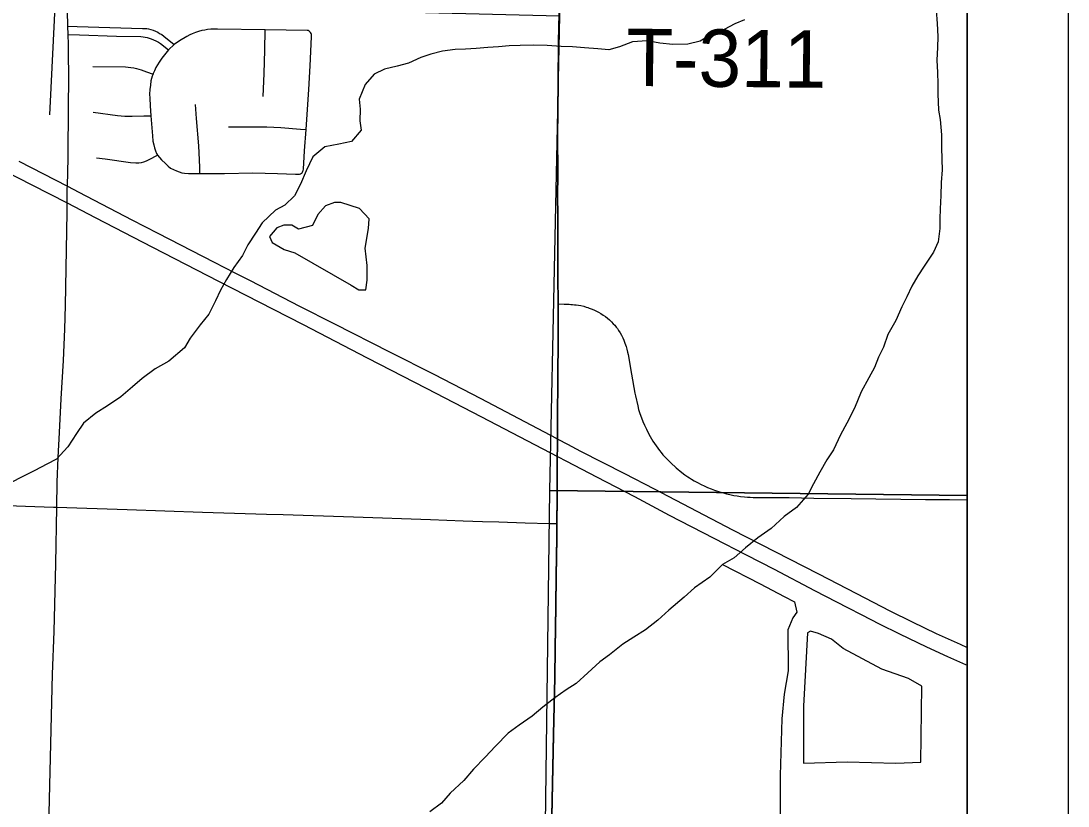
# Model space of a CAD drawing. Extents: x 0 to 34, y 0 to 22.
# Drawn here: x 7.962 to 9, y 16.1 to 16.878 of the extents above; entities that cross this region are included whole.
import ezdxf

# ---------------------------------------------------------------- set-up
doc = ezdxf.new("R2010")
doc.units = 0
for name, color, linetype in [('GM_X_Corporation', 7, 'Continuous'), ('GM_X_County_Road', 7, 'Continuous'), ('GM_X_Interstate_Route', 7, 'Continuous'), ('GM_X_Minor_Lake', 7, 'Continuous'), ('GM_X_Minor_River', 7, 'Continuous'), ('GM_X_Township_Road', 7, 'Continuous'), ('GM_X_Township_Road_Text', 7, 'Continuous'), ('SH_Data', 7, 'Continuous')]:
    doc.layers.add(name, color=color, linetype=linetype)

msp = doc.modelspace()

# ---------------------------------------------------------------- linework, layer by layer
at = {"layer": 'GM_X_Corporation'}
for points in [[(2.1, 14.1), (8.9, 14.1), (8.9, 20.9), (5.8906, 20.9)], [(8.9, 14.3789), (8.9, 20.9)], [(8.496, 16.9136), (8.4946, 16.8569), (8.4944, 16.8165), (8.4939, 16.763), (8.494, 16.7276), (8.4939, 16.7021), (8.494, 16.6872), (8.4942, 16.6244), (8.4943, 16.5979), (8.4943, 16.5579), (8.494, 16.5287), (8.4938, 16.4783), (8.4937, 16.4639), (8.4937, 16.4541), (8.4936, 16.4468), (8.4936, 16.4298), (8.4936, 16.405), (8.4932, 16.3802), (8.493, 16.3658), (8.4926, 16.3279), (8.4922, 16.2981), (8.4916, 16.2558), (8.491, 16.2272), (8.4897, 16.1707), (8.4889, 16.1222), (8.4875, 16.0575)], [(8.4875, 16.0575), (8.4889, 16.1222), (8.4897, 16.1707), (8.491, 16.2272), (8.4916, 16.2558), (8.4922, 16.2981), (8.4926, 16.3279), (8.493, 16.3658), (8.4932, 16.3802), (8.4936, 16.405), (8.4936, 16.4298), (8.4936, 16.4468), (8.4937, 16.4541), (8.4937, 16.4639), (8.4938, 16.4783), (8.494, 16.5287), (8.4943, 16.5579), (8.4943, 16.5979), (8.4942, 16.6244), (8.494, 16.6872), (8.4939, 16.7021), (8.494, 16.7276), (8.4939, 16.763), (8.4944, 16.8165), (8.4946, 16.8569), (8.496, 16.9136)]]:
    msp.add_lwpolyline(points, dxfattribs=at)
for points in [[(8.9, 16.4075), (8.9, 17.4164), (8.5049, 17.4227), (8.4956, 16.8828), (8.4859, 16.4125)], [(7.4991, 16.9078), (8.4956, 16.8828), (8.4859, 16.4125), (8.4788, 15.8782), (7.4758, 15.8976)], [(8.9, 15.399), (8.9, 16.4075), (8.4859, 16.4125), (8.4788, 15.8782), (8.4721, 15.4049)]]:
    msp.add_lwpolyline(points, close=True, dxfattribs=at)
at = {"layer": 'GM_X_County_Road'}
for points in [[(8.0086, 16.8642), (8.0084, 16.8726), (8.0076, 16.9023), (8.0071, 16.9257)], [(8.4945, 16.5973), (8.4945, 16.6238), (8.4942, 16.6866), (8.4941, 16.7015), (8.4942, 16.727), (8.4942, 16.7625), (8.4946, 16.8159), (8.4948, 16.8563), (8.4962, 16.913)], [(8.0089, 16.8495), (8.0088, 16.8545), (8.0086, 16.8642)], [(8.0077, 16.7055), (8.0077, 16.7116), (8.0078, 16.7138), (8.0085, 16.7421), (8.0089, 16.7947), (8.0092, 16.8187), (8.0089, 16.8495)], [(7.9972, 16.3958), (7.9977, 16.4207), (7.9986, 16.445), (8, 16.4698), (8.0016, 16.5033), (8.004, 16.5412), (8.0053, 16.5722), (8.0061, 16.5958), (8.0075, 16.688), (8.0076, 16.6973), (8.0077, 16.7055)], [(8.4939, 16.4452), (8.4939, 16.4462), (8.4939, 16.4535), (8.494, 16.4634), (8.494, 16.4778), (8.4942, 16.5281), (8.4946, 16.5573), (8.4945, 16.5973)], [(8.4935, 16.3796), (8.4938, 16.4044), (8.4938, 16.4293), (8.4939, 16.4452)], [(7.9851, 15.8887), (7.9866, 15.9593), (7.9884, 16.0454), (7.9898, 16.0926), (7.9932, 16.2305), (7.9946, 16.2726), (7.9962, 16.3398), (7.9972, 16.3958)], [(8.4846, 15.8731), (8.4847, 15.8798), (8.4861, 15.9587), (8.4873, 16.029), (8.4877, 16.057), (8.4891, 16.1216), (8.49, 16.1701), (8.4912, 16.2267), (8.4918, 16.2553), (8.4924, 16.2975), (8.4928, 16.3274), (8.4933, 16.3653), (8.4935, 16.3796)]]:
    msp.add_lwpolyline(points, dxfattribs=at)
at = {"layer": 'GM_X_Interstate_Route'}
for points in [[(7.8766, 16.7643), (7.9724, 16.7153), (8.0076, 16.6973), (8.0355, 16.683), (8.0923, 16.6534), (8.1575, 16.6198), (8.2117, 16.592), (8.2417, 16.5768), (8.3052, 16.544), (8.3637, 16.5137), (8.4184, 16.4854), (8.4939, 16.4462), (8.5028, 16.4415), (8.5326, 16.4261), (8.57, 16.4063), (8.6046, 16.388), (8.6488, 16.3651), (8.6808, 16.3486)], [(7.9596, 16.7389), (8.0078, 16.7138), (8.0192, 16.7079), (8.0716, 16.6807), (8.0976, 16.6673), (8.1535, 16.6386), (8.1739, 16.628), (8.1889, 16.6204), (8.238, 16.595), (8.2719, 16.578), (8.3279, 16.5495), (8.3711, 16.5276), (8.4176, 16.5036), (8.4926, 16.4641), (8.494, 16.4634), (8.5038, 16.4582), (8.5166, 16.4515), (8.5603, 16.4291), (8.5896, 16.414), (8.6673, 16.3735), (8.6952, 16.3593)], [(8.6952, 16.3593), (8.7526, 16.3299), (8.7901, 16.3103), (8.8232, 16.2932), (8.8455, 16.2821), (8.8691, 16.2708), (8.8929, 16.26), (8.9, 16.2569)], [(8.6808, 16.3486), (8.7085, 16.3344), (8.7487, 16.3134), (8.7813, 16.2965), (8.7956, 16.2891), (8.8128, 16.2804), (8.8329, 16.2704), (8.8597, 16.2574), (8.8806, 16.2478), (8.8982, 16.24), (8.9, 16.2392)]]:
    msp.add_lwpolyline(points, dxfattribs=at)
at = {"layer": 'GM_X_Minor_Lake'}
for p, q in [((8.2334, 16.6479), (8.2893, 16.6157)), ((8.8294, 16.1421), (8.854, 16.1433))]:
    msp.add_line(p, q, dxfattribs=at)
for points in [[(8.2893, 16.6157), (8.2968, 16.6111), (8.3036, 16.6114), (8.3049, 16.6209), (8.305, 16.6353), (8.303, 16.6524), (8.3063, 16.6721), (8.3072, 16.6816), (8.2975, 16.6919), (8.279, 16.6978), (8.2726, 16.6979), (8.2639, 16.6946), (8.2562, 16.686), (8.2508, 16.6751), (8.2371, 16.6714), (8.2304, 16.6753), (8.2225, 16.6754), (8.2156, 16.6728), (8.2083, 16.6642), (8.2109, 16.6581), (8.2229, 16.6511), (8.2334, 16.6479)], [(8.854, 16.1433), (8.855, 16.2184), (8.8418, 16.2262), (8.8155, 16.2352), (8.7769, 16.2558), (8.7653, 16.2651), (8.7525, 16.2706), (8.7446, 16.273), (8.7416, 16.2715), (8.7376, 16.1986), (8.7376, 16.1421), (8.7811, 16.1434), (8.8294, 16.1421)]]:
    msp.add_lwpolyline(points, dxfattribs=at)
at = {"layer": 'GM_X_Minor_River'}
for points in [[(7.2928, 17.8115), (7.3401, 17.8018), (7.3986, 17.7904), (7.4434, 17.7823), (7.5003, 17.7732), (7.5467, 17.7696), (7.6442, 17.7695), (7.7568, 17.7696), (7.8864, 17.7695), (7.9974, 17.77), (8.0144, 17.766), (8.0173, 17.7591), (8.0181, 17.7348), (8.0147, 17.6168), (8.0142, 17.4615), (8.0102, 17.2942), (8.0074, 17.1093), (7.9961, 16.9056), (7.99, 16.7846)], [(8.8693, 16.8882), (8.8703, 16.8752), (8.8709, 16.8623), (8.8704, 16.8513), (8.8698, 16.8388), (8.8704, 16.8267), (8.871, 16.8153), (8.8709, 16.8054), (8.8714, 16.7894), (8.8732, 16.7799), (8.8745, 16.7647), (8.8744, 16.7526), (8.875, 16.7404), (8.8752, 16.7302), (8.8743, 16.7177), (8.8737, 16.7048), (8.8732, 16.6915), (8.8727, 16.6816), (8.8729, 16.6721), (8.8713, 16.6589), (8.8666, 16.6487), (8.8573, 16.6348), (8.8512, 16.625), (8.845, 16.6148), (8.8403, 16.6042), (8.8353, 16.5944), (8.8291, 16.5808)], [(8.6792, 16.8788), (8.6697, 16.8747), (8.659, 16.8692), (8.6476, 16.8648), (8.6351, 16.8577), (8.623, 16.8548), (8.6082, 16.8543), (8.5954, 16.8556), (8.5826, 16.858), (8.5682, 16.857), (8.5553, 16.8519), (8.5447, 16.849), (8.5337, 16.8499), (8.5205, 16.8512), (8.5088, 16.8521), (8.4975, 16.8522), (8.4835, 16.8532), (8.4699, 16.8537), (8.4567, 16.8535), (8.4458, 16.8529), (8.4352, 16.8519), (8.4246, 16.8513), (8.4132, 16.8503), (8.4026, 16.8496), (8.3924, 16.8494), (8.3796, 16.8477), (8.3682, 16.8448), (8.3583, 16.8415), (8.3462, 16.8359), (8.3348, 16.833), (8.3223, 16.8298), (8.312, 16.825), (8.3032, 16.8148), (8.297, 16.8001), (8.298, 16.7902), (8.2978, 16.7788), (8.2992, 16.7693), (8.2896, 16.7581), (8.2768, 16.7556), (8.2631, 16.7531), (8.2513, 16.743), (8.2447, 16.729), (8.2388, 16.7158), (8.233, 16.7045), (8.2235, 16.6951), (8.214, 16.6903), (8.201, 16.6776), (8.1944, 16.6674), (8.1867, 16.6557), (8.1813, 16.6452), (8.1728, 16.6335), (8.1655, 16.6215), (8.1597, 16.6109), (8.1546, 16.6004), (8.148, 16.5871), (8.1396, 16.5766), (8.1296, 16.5635), (8.1238, 16.5537), (8.1085, 16.5406), (8.0948, 16.5328), (8.0818, 16.5235), (8.0723, 16.5152), (8.0608, 16.5051), (8.0475, 16.4962), (8.0361, 16.4891), (8.0238, 16.479), (8.0169, 16.4689), (8.0084, 16.4557), (7.9969, 16.4433), (7.9874, 16.4385), (7.9756, 16.4322), (7.9623, 16.4255), (7.9528, 16.4207)], [(8.8291, 16.5808), (8.8213, 16.5669), (8.817, 16.5544), (8.812, 16.5446), (8.8081, 16.5344), (8.8026, 16.5242), (8.7949, 16.5103), (8.7883, 16.4941), (8.7805, 16.479), (8.7743, 16.4677), (8.7673, 16.4526), (8.7608, 16.4428), (8.7538, 16.4307), (8.7476, 16.419), (8.7422, 16.4089), (8.7307, 16.3957), (8.7185, 16.3868), (8.7055, 16.3748), (8.6925, 16.3655), (8.6803, 16.3557), (8.6689, 16.3456), (8.6574, 16.339), (8.6448, 16.3266), (8.6296, 16.3158), (8.6192, 16.3068), (8.6043, 16.2937), (8.5933, 16.284), (8.581, 16.2743), (8.5696, 16.2672), (8.5586, 16.2601), (8.5452, 16.2497), (8.5357, 16.2426), (8.5238, 16.2317), (8.5124, 16.2212), (8.5025, 16.2149), (8.491, 16.2071), (8.4792, 16.1977), (8.4685, 16.1888), (8.4559, 16.1798), (8.4449, 16.172), (8.4322, 16.1592), (8.4219, 16.148), (8.4104, 16.1364), (8.4008, 16.1251), (8.3874, 16.1124), (8.3786, 16.1026), (8.3671, 16.094)], [(8.6574, 16.339), (8.6946, 16.3199), (8.7186, 16.3074), (8.7287, 16.302), (8.7312, 16.2917), (8.727, 16.2861), (8.722, 16.2744), (8.7226, 16.2338), (8.7185, 16.2107), (8.7163, 16.186), (8.7144, 16.1299), (8.7149, 16.0524)]]:
    msp.add_lwpolyline(points, dxfattribs=at)
at = {"layer": 'GM_X_Township_Road'}
msp.add_line((8.1136, 16.8542), (8.108, 16.849), dxfattribs=at)
for points in [[(8.0084, 16.8726), (8.0175, 16.8723), (8.0824, 16.8703), (8.0866, 16.8701), (8.0884, 16.8698), (8.0904, 16.8693), (8.0928, 16.8685), (8.0953, 16.8675), (8.0974, 16.8665), (8.0993, 16.8654), (8.1014, 16.8641), (8.1033, 16.8626), (8.1136, 16.8542)], [(8.0086, 16.8642), (8.0198, 16.8638), (8.0565, 16.8627), (8.0805, 16.8622), (8.0829, 16.862), (8.0848, 16.8617), (8.087, 16.8612), (8.0889, 16.8606), (8.0909, 16.8599), (8.0931, 16.859), (8.0956, 16.8579), (8.098, 16.8566), (8.1, 16.8554), (8.108, 16.849)], [(8.204, 16.869), (8.1566, 16.8695), (8.153, 16.8696), (8.1499, 16.8695), (8.1469, 16.8691), (8.1441, 16.8687), (8.1412, 16.8681), (8.1378, 16.8673), (8.1347, 16.8663), (8.1315, 16.865), (8.1291, 16.8638), (8.1262, 16.8624), (8.1191, 16.858), (8.1136, 16.8542)], [(8.202, 16.8029), (8.2028, 16.8255), (8.2035, 16.8487), (8.204, 16.869)], [(8.2445, 16.77), (8.2472, 16.8096), (8.2484, 16.8333), (8.2498, 16.8621), (8.2498, 16.863), (8.2497, 16.8642), (8.2494, 16.8652), (8.2489, 16.8662), (8.2483, 16.867), (8.2476, 16.8676), (8.2465, 16.8681), (8.2457, 16.8683), (8.204, 16.869)], [(8.108, 16.849), (8.1016, 16.8407), (8.0988, 16.8367), (8.0971, 16.8341), (8.0956, 16.8315), (8.0942, 16.8284), (8.093, 16.8257), (8.0928, 16.8251)], [(8.0329, 16.8325), (8.0655, 16.8321), (8.0681, 16.8319), (8.0706, 16.8316), (8.0736, 16.8311), (8.0762, 16.8306), (8.0786, 16.83), (8.0809, 16.8292), (8.0861, 16.8274), (8.0928, 16.8251)], [(8.0928, 16.8251), (8.0919, 16.8229), (8.0907, 16.8182), (8.0901, 16.8142), (8.0896, 16.8099), (8.0893, 16.805), (8.0895, 16.8012), (8.0899, 16.7935), (8.0906, 16.7838)], [(8.139, 16.7264), (8.139, 16.7323), (8.1389, 16.7402), (8.1383, 16.7539), (8.1359, 16.7811), (8.1347, 16.7949)], [(8.0335, 16.7874), (8.0574, 16.784), (8.0648, 16.7833), (8.072, 16.7832), (8.0835, 16.7835), (8.0906, 16.7838)], [(8.0906, 16.7838), (8.0921, 16.7639), (8.0927, 16.7584), (8.0935, 16.755), (8.0942, 16.7521), (8.0952, 16.7491), (8.0963, 16.7464), (8.0973, 16.7447)], [(8.139, 16.7264), (8.1636, 16.7265), (8.1916, 16.7272), (8.216, 16.7266), (8.234, 16.7257), (8.2358, 16.7257), (8.237, 16.7257), (8.238, 16.7259), (8.239, 16.7263), (8.2399, 16.7268), (8.2405, 16.7273), (8.241, 16.728), (8.2414, 16.7287), (8.2417, 16.7295), (8.2418, 16.7307), (8.243, 16.749), (8.2445, 16.77)], [(8.1676, 16.7727), (8.1896, 16.7726), (8.2057, 16.7727), (8.2195, 16.772), (8.2388, 16.7705), (8.2445, 16.77)], [(8.0367, 16.742), (8.0454, 16.741), (8.0705, 16.7374), (8.0757, 16.737), (8.0787, 16.7371), (8.0814, 16.7375), (8.0836, 16.7381), (8.0863, 16.7391), (8.089, 16.7404), (8.0973, 16.7447)], [(8.0973, 16.7447), (8.099, 16.7425), (8.1011, 16.7402), (8.105, 16.7363), (8.1078, 16.7338), (8.1102, 16.7319), (8.113, 16.7304), (8.1159, 16.729), (8.1186, 16.7281), (8.1212, 16.7273), (8.1241, 16.7268), (8.1278, 16.7264), (8.139, 16.7264)], [(8.4939, 16.4452), (8.4939, 16.4462), (8.4939, 16.4535), (8.494, 16.4634), (8.494, 16.4778), (8.4942, 16.5281), (8.4946, 16.5573), (8.4945, 16.5973)], [(8.4945, 16.5973), (8.5005, 16.5971), (8.5054, 16.5969), (8.5069, 16.5968), (8.5088, 16.5967), (8.5106, 16.5965), (8.5122, 16.5964), (8.5147, 16.596), (8.517, 16.5956), (8.5199, 16.5949), (8.5223, 16.5942), (8.5238, 16.5937), (8.5252, 16.5932), (8.5281, 16.5922), (8.5303, 16.5912), (8.5326, 16.5902), (8.5345, 16.5892), (8.5369, 16.5878), (8.5391, 16.5863), (8.5414, 16.5847), (8.5432, 16.5833), (8.5452, 16.5816), (8.5473, 16.5796), (8.5491, 16.5777), (8.5505, 16.5761), (8.5519, 16.5744), (8.5531, 16.5728), (8.5544, 16.571), (8.5559, 16.5685), (8.5572, 16.5662), (8.5584, 16.5637), (8.5595, 16.5612), (8.5607, 16.5583), (8.5618, 16.5551), (8.5625, 16.5526), (8.5633, 16.5496), (8.5637, 16.5472), (8.5644, 16.5436), (8.5652, 16.5392), (8.5672, 16.5276), (8.5706, 16.509)], [(8.5706, 16.509), (8.5711, 16.5061), (8.5733, 16.4964), (8.5741, 16.4928), (8.5754, 16.4888), (8.577, 16.4844), (8.5785, 16.4808), (8.5801, 16.477), (8.5819, 16.4733), (8.5837, 16.4696), (8.5857, 16.466), (8.5883, 16.4614), (8.5915, 16.4567), (8.5931, 16.4543), (8.5949, 16.452), (8.5964, 16.4501), (8.5983, 16.4478), (8.6004, 16.4455), (8.6029, 16.443), (8.6062, 16.4397), (8.6113, 16.435), (8.6171, 16.4302), (8.62, 16.428), (8.6229, 16.426), (8.6246, 16.4249), (8.6266, 16.4236), (8.6294, 16.422), (8.6326, 16.4203), (8.6361, 16.4184), (8.6391, 16.417), (8.6425, 16.4155), (8.646, 16.414), (8.6495, 16.4128), (8.6533, 16.4115), (8.6573, 16.4103), (8.6614, 16.4092), (8.6646, 16.4084), (8.6687, 16.4076), (8.6719, 16.407), (8.6752, 16.4065), (8.6792, 16.4061), (8.6821, 16.4059), (8.6849, 16.4057), (8.6878, 16.4056)], [(8.4935, 16.3796), (8.4938, 16.4044), (8.4938, 16.4293), (8.4939, 16.4452)], [(6.9807, 16.4115), (6.9883, 16.4114), (7.0616, 16.4104), (7.1474, 16.4098), (7.2161, 16.4092), (7.2571, 16.4093), (7.3355, 16.4101), (7.3641, 16.4105), (7.4261, 16.4113), (7.4732, 16.4118), (7.4925, 16.4118), (7.5142, 16.4114), (7.5583, 16.4099), (7.6882, 16.4061), (7.741, 16.4042), (7.8256, 16.4018), (7.9293, 16.3982), (7.9939, 16.3959), (7.9972, 16.3958)], [(8.6878, 16.4056), (8.6897, 16.4056), (8.6962, 16.4054), (8.7236, 16.4053), (8.7478, 16.4049), (8.7848, 16.4045), (8.8588, 16.4035), (8.8824, 16.4035), (8.9, 16.4032)], [(7.9972, 16.3958), (8.0672, 16.3937), (8.1417, 16.391), (8.2051, 16.3889), (8.2219, 16.3885), (8.2915, 16.3862), (8.3679, 16.3836), (8.4002, 16.3824), (8.4195, 16.3817), (8.4357, 16.3813), (8.4618, 16.3805), (8.486, 16.3798), (8.4935, 16.3796)]]:
    msp.add_lwpolyline(points, dxfattribs=at)
at = {"layer": 'SH_Data'}
for p, q in [((9, 21), (9, 14)), ((9, 21), (9, 14)), ((8.9, 20.9), (8.9, 14.1)), ((8.9, 20.9), (8.9, 14.1))]:
    msp.add_line(p, q, dxfattribs=at)

# ---------------------------------------------------------------- texts
at = {"layer": 'GM_X_Township_Road_Text'}
msp.add_text('T-311', height=0.05682, rotation=359.4392, dxfattribs=at).set_placement((8.5617, 16.8133))

doc.saveas('drawing.dxf')
